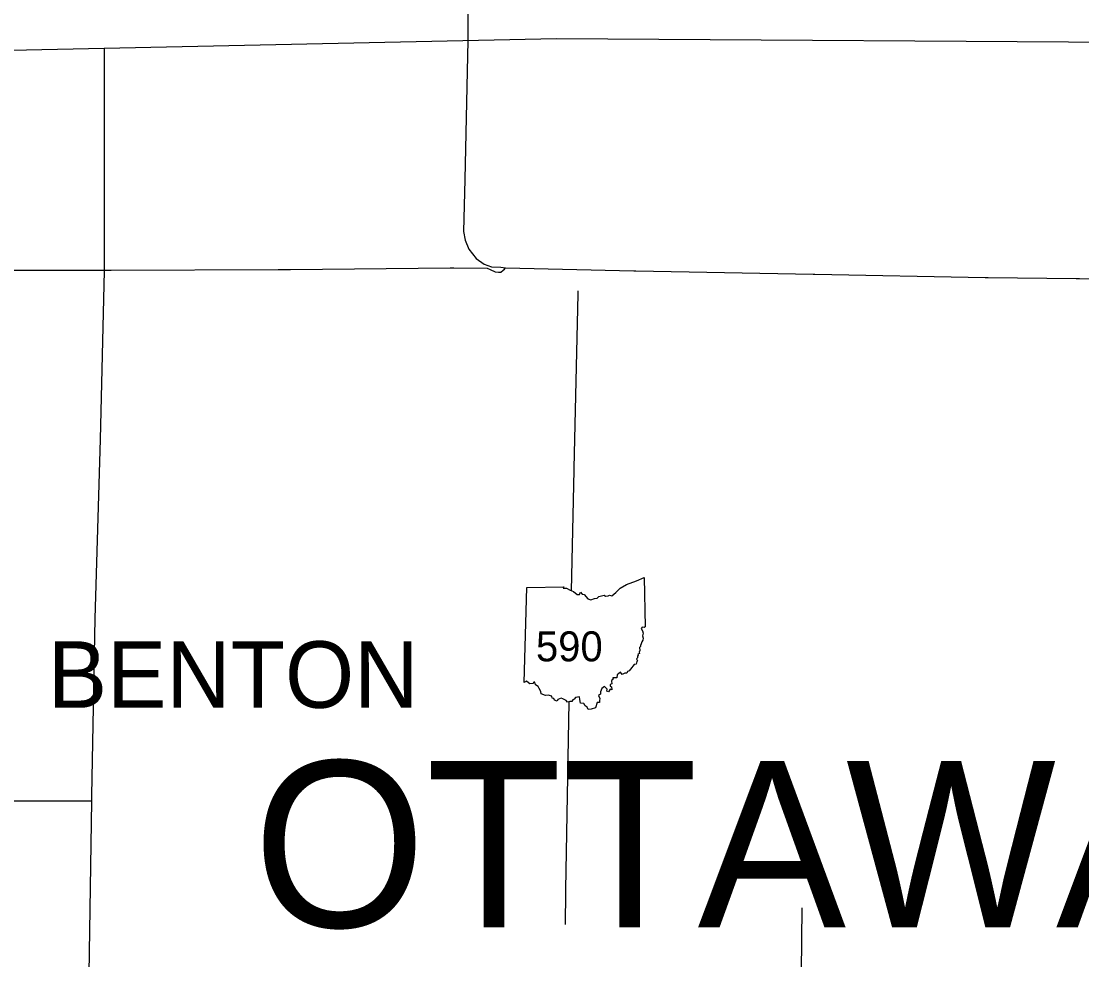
# Model space of a CAD drawing. Extents: x -232 to 448, y 619 to 1059.
# Drawn here: x 239.07 to 271.78, y 890.09 to 919.03 of the extents above; entities that cross this region are included whole.
import ezdxf

# ---------------------------------------------------------------- set-up
doc = ezdxf.new("R2010")
doc.units = 0
doc.layers.add('Default', color=7, linetype='Continuous')

msp = doc.modelspace()

# ---------------------------------------------------------------- linework, layer by layer
at = {"layer": 'Default'}
msp.add_line((254.581, 898.64), (254.663, 901.569), dxfattribs=at)
msp.add_line((254.581, 898.64), (254.663, 901.569), dxfattribs=at)
for points in [[(243.626, 924.477), (247.327, 924.406), (249.08, 924.426), (251.324, 924.39), (251.738, 924.342), (252.026, 924.24), (252.25, 924.099), (252.444, 923.93), (252.58, 923.792), (252.72, 923.564), (252.799, 923.328), (252.85, 923.043), (252.848, 918.436)], [(241.621, 918.197), (255.575, 918.495), (274.524, 918.377)], [(252.848, 918.436), (252.751, 914.153)], [(220.494, 917.745), (241.621, 918.197)], [(241.621, 918.197), (241.621, 911.333), (241.503, 906.136), (241.333, 900.609), (241.237, 895.158), (241.234, 894.977)], [(252.751, 914.153), (252.714, 912.548), (252.757, 912.282), (252.874, 912.008), (253.099, 911.716), (253.351, 911.539), (253.57, 911.461), (253.861, 911.447), (254.01, 911.427), (257.964, 911.334), (258.021, 911.332), (263.493, 911.237), (263.548, 911.236)], [(231.812, 911.388), (235.823, 911.359), (235.867, 911.358), (235.931, 911.358), (241.731, 911.356), (241.74, 911.355), (241.784, 911.355)], [(241.784, 911.355), (241.839, 911.355), (246.989, 911.372), (247.019, 911.372), (247.097, 911.372), (247.368, 911.375)], [(247.368, 911.375), (252.3, 911.426), (252.34, 911.426), (252.409, 911.425), (253.438, 911.419), (253.44, 911.418), (253.537, 911.373), (253.684, 911.304), (253.691, 911.301), (253.792, 911.295), (253.846, 911.292), (253.865, 911.291), (253.93, 911.352), (253.97, 911.389), (254.01, 911.427)], [(263.548, 911.236), (268.802, 911.127), (268.896, 911.125), (271.605, 911.101), (271.711, 911.1), (274.364, 911.019), (274.454, 911.016), (279.438, 911.028), (279.505, 911.028), (284.814, 911.012), (284.814, 911.012), (284.826, 911.012)], [(256.037, 901.469), (256.125, 905.192), (256.125, 905.25), (256.245, 910.612), (256.245, 910.612), (256.247, 910.719)], [(254.663, 901.569), (255.8, 901.588), (255.782, 901.552), (255.889, 901.545), (256.003, 901.483), (256.099, 901.443), (256.217, 901.35), (256.288, 901.351), (256.317, 901.427), (256.371, 901.368), (256.435, 901.358), (256.546, 901.218), (256.638, 901.187), (256.747, 901.235), (256.829, 901.243), (256.889, 901.291), (257.045, 901.331), (257.088, 901.307), (257.171, 901.312), (257.212, 901.33), (257.284, 901.314), (257.411, 901.42), (257.542, 901.546), (257.742, 901.664), (258.042, 901.777), (258.279, 901.877), (258.314, 900.357)], [(254.663, 901.569), (255.8, 901.588), (255.782, 901.552), (255.889, 901.545), (256.003, 901.483), (256.099, 901.443), (256.217, 901.35), (256.288, 901.351), (256.317, 901.427), (256.371, 901.368), (256.435, 901.358), (256.546, 901.218), (256.638, 901.187), (256.747, 901.235), (256.829, 901.243), (256.889, 901.291), (257.045, 901.331), (257.088, 901.307), (257.171, 901.312), (257.212, 901.33), (257.284, 901.314), (257.411, 901.42), (257.542, 901.546), (257.742, 901.664), (258.042, 901.777), (258.279, 901.877), (258.314, 900.357)], [(258.314, 900.357), (258.279, 900.336), (258.224, 900.346), (258.187, 900.303), (258.233, 900.232), (258.254, 900.157), (258.235, 900.074), (258.254, 900.006), (258.241, 899.949), (258.207, 899.892), (258.195, 899.837), (258.166, 899.78), (258.168, 899.748), (258.141, 899.723), (258.146, 899.628), (258.132, 899.575), (258.137, 899.53), (258.092, 899.518), (258.102, 899.48), (258.073, 899.451), (258.079, 899.401), (258.047, 899.37), (258.078, 899.306), (258.053, 899.286), (258.032, 899.208), (257.974, 899.192), (257.859, 899.05), (257.818, 898.997), (257.772, 898.983), (257.747, 898.928), (257.691, 898.928), (257.605, 898.89), (257.55, 898.956), (257.453, 898.877), (257.442, 898.785), (257.32, 898.788), (257.325, 898.742), (257.297, 898.729), (257.273, 898.682), (257.287, 898.6), (257.23, 898.579), (257.237, 898.531), (257.273, 898.502), (257.29, 898.411), (257.229, 898.43), (257.179, 898.353), (257.128, 898.371), (257.145, 898.436), (257.058, 898.514), (256.976, 898.451), (256.933, 898.351), (256.933, 898.284), (256.872, 898.243), (256.911, 898.148), (256.904, 898.082), (256.905, 898.02), (256.829, 898.022), (256.783, 897.854)], [(258.314, 900.357), (258.279, 900.336), (258.224, 900.346), (258.187, 900.303), (258.233, 900.232), (258.254, 900.157), (258.235, 900.074), (258.254, 900.006), (258.241, 899.949), (258.207, 899.892), (258.195, 899.837), (258.166, 899.78), (258.168, 899.748), (258.141, 899.723), (258.146, 899.628), (258.132, 899.575), (258.137, 899.53), (258.092, 899.518), (258.102, 899.48), (258.073, 899.451), (258.079, 899.401), (258.047, 899.37), (258.078, 899.306), (258.053, 899.286), (258.032, 899.208), (257.974, 899.192), (257.859, 899.05), (257.818, 898.997), (257.772, 898.983), (257.747, 898.928), (257.691, 898.928), (257.605, 898.89), (257.55, 898.956), (257.453, 898.877), (257.442, 898.785), (257.32, 898.788), (257.325, 898.742), (257.297, 898.729), (257.273, 898.682), (257.287, 898.6), (257.23, 898.579), (257.237, 898.531), (257.273, 898.502), (257.29, 898.411), (257.229, 898.43), (257.179, 898.353), (257.128, 898.371), (257.145, 898.436), (257.058, 898.514), (256.976, 898.451), (256.933, 898.351), (256.933, 898.284), (256.872, 898.243), (256.911, 898.148), (256.904, 898.082), (256.905, 898.02), (256.829, 898.022), (256.783, 897.854)], [(256.783, 897.854), (256.65, 897.822), (256.558, 897.803), (256.525, 897.879), (256.46, 897.919), (256.417, 897.996), (256.322, 898.007), (256.3, 898.112), (256.289, 898.198), (256.16, 898.177), (256.124, 898.124), (256.079, 898.11), (256.052, 898.057), (255.99, 898.053), (255.922, 898.028), (255.879, 898.08), (255.769, 898.132), (255.719, 898.159), (255.616, 898.117), (255.594, 898.068), (255.512, 898.09), (255.493, 898.145), (255.443, 898.161), (255.432, 898.219), (255.326, 898.25), (255.244, 898.238), (255.101, 898.285), (255.092, 898.362), (255.043, 898.455), (255.018, 898.52), (254.927, 898.57), (254.909, 898.647), (254.88, 898.645), (254.853, 898.613), (254.752, 898.599), (254.712, 898.631), (254.656, 898.684), (254.581, 898.64)], [(256.783, 897.854), (256.65, 897.822), (256.558, 897.803), (256.525, 897.879), (256.46, 897.919), (256.417, 897.996), (256.322, 898.007), (256.3, 898.112), (256.289, 898.198), (256.16, 898.177), (256.124, 898.124), (256.079, 898.11), (256.052, 898.057), (255.99, 898.053), (255.922, 898.028), (255.879, 898.08), (255.769, 898.132), (255.719, 898.159), (255.616, 898.117), (255.594, 898.068), (255.512, 898.09), (255.493, 898.145), (255.443, 898.161), (255.432, 898.219), (255.326, 898.25), (255.244, 898.238), (255.101, 898.285), (255.092, 898.362), (255.043, 898.455), (255.018, 898.52), (254.927, 898.57), (254.909, 898.647), (254.88, 898.645), (254.853, 898.613), (254.752, 898.599), (254.712, 898.631), (254.656, 898.684), (254.581, 898.64)], [(255.858, 891.174), (255.868, 892.17), (255.868, 892.257), (255.968, 898.045)], [(241.234, 894.977), (235.605, 894.982), (230.248, 895.042), (224.835, 895.064), (208.972, 895.219)], [(241.234, 894.977), (241.156, 889.655), (241.062, 884.206), (240.982, 878.692)], [(263.107, 886.738), (263.159, 891.691)]]:
    msp.add_lwpolyline(points, dxfattribs=at)

# ---------------------------------------------------------------- texts
for s, height, p in [('590', 0.9234, (254.944, 899.293)), ('BENTON', 2.052, (239.885, 897.859)), ('OTTAWA', 5.13, (246.217, 891.091))]:
    msp.add_text(s, height=height, dxfattribs=at).set_placement(p)

doc.saveas('drawing.dxf')
